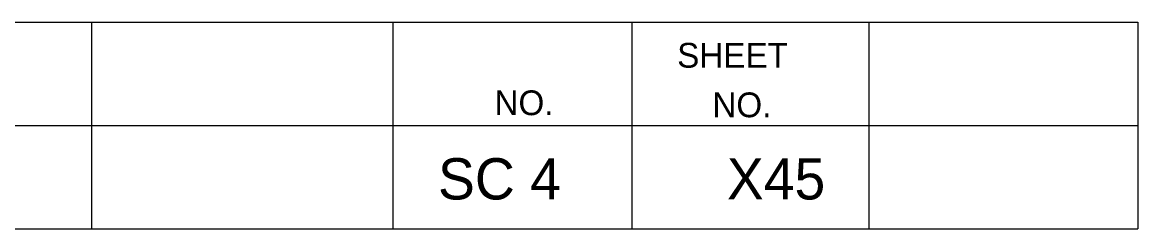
# Model space of a CAD drawing. Extents: x 1000 to 1162, y 999 to 8520.
# Drawn here: x 1148.08 to 1161.56, y 6160.05 to 6162.55 of the extents above; entities that cross this region are included whole.
import ezdxf

# ---------------------------------------------------------------- set-up
doc = ezdxf.new("R2010")
doc.units = 0
doc.layers.add('Level 20', color=7, linetype='Continuous')
doc.layers.add('Level 3', color=7, linetype='Continuous')

msp = doc.modelspace()

# ---------------------------------------------------------------- linework, layer by layer
at = {"layer": 'Level 3'}
for p, q in [((1133.055, 6162.546), (1161.555, 6162.546)), ((1133.055, 6162.546), (1161.555, 6162.546)), ((1133.055, 6162.546), (1161.555, 6162.546)), ((1133.055, 6162.546), (1161.555, 6162.546)), ((1133.055, 6162.546), (1161.555, 6162.546)), ((1133.055, 6162.546), (1161.555, 6162.546)), ((1133.055, 6162.546), (1161.555, 6162.546)), ((1133.055, 6162.546), (1161.555, 6162.546)), ((1133.055, 6162.546), (1161.555, 6162.546)), ((1133.055, 6162.546), (1161.555, 6162.546)), ((1133.055, 6162.546), (1161.555, 6162.546)), ((1133.055, 6162.546), (1161.555, 6162.546)), ((1133.055, 6162.546), (1161.555, 6162.546)), ((1133.055, 6162.546), (1161.555, 6162.546)), ((1133.055, 6162.546), (1161.555, 6162.546)), ((1133.055, 6162.546), (1161.555, 6162.546)), ((1133.055, 6162.546), (1161.555, 6162.546)), ((1133.055, 6162.546), (1161.555, 6162.546)), ((1133.055, 6162.546), (1161.555, 6162.546)), ((1133.055, 6162.546), (1161.555, 6162.546)), ((1133.055, 6162.546), (1161.555, 6162.546)), ((1133.055, 6162.546), (1161.555, 6162.546)), ((1133.055, 6162.546), (1161.555, 6162.546)), ((1133.055, 6162.546), (1161.555, 6162.546)), ((1133.055, 6162.546), (1161.555, 6162.546)), ((1133.055, 6162.546), (1161.555, 6162.546)), ((1133.055, 6162.546), (1161.555, 6162.546)), ((1133.055, 6162.546), (1161.555, 6162.546)), ((1133.055, 6162.546), (1161.555, 6162.546)), ((1133.055, 6162.546), (1161.555, 6162.546)), ((1133.055, 6162.546), (1161.555, 6162.546)), ((1133.055, 6162.546), (1161.555, 6162.546)), ((1133.055, 6162.546), (1161.555, 6162.546)), ((1133.055, 6162.546), (1161.555, 6162.546)), ((1133.055, 6162.546), (1161.555, 6162.546)), ((1133.055, 6162.546), (1161.555, 6162.546)), ((1133.055, 6162.546), (1161.555, 6162.546)), ((1133.055, 6162.546), (1161.555, 6162.546)), ((1133.055, 6162.546), (1161.555, 6162.546)), ((1133.055, 6162.546), (1161.555, 6162.546)), ((1133.055, 6162.546), (1161.555, 6162.546)), ((1133.055, 6162.546), (1161.555, 6162.546)), ((1133.055, 6162.546), (1161.555, 6162.546)), ((1148.913, 6162.546), (1148.913, 6160.046)), ((1148.913, 6162.546), (1148.913, 6160.046)), ((1148.913, 6162.546), (1148.913, 6160.046)), ((1148.913, 6162.546), (1148.913, 6160.046)), ((1148.913, 6162.546), (1148.913, 6160.046)), ((1148.913, 6162.546), (1148.913, 6160.046)), ((1148.913, 6162.546), (1148.913, 6160.046)), ((1148.913, 6162.546), (1148.913, 6160.046)), ((1148.913, 6162.546), (1148.913, 6160.046)), ((1148.913, 6162.546), (1148.913, 6160.046)), ((1148.913, 6162.546), (1148.913, 6160.046)), ((1148.913, 6162.546), (1148.913, 6160.046)), ((1148.913, 6162.546), (1148.913, 6160.046)), ((1148.913, 6162.546), (1148.913, 6160.046)), ((1148.913, 6162.546), (1148.913, 6160.046)), ((1148.913, 6162.546), (1148.913, 6160.046)), ((1148.913, 6162.546), (1148.913, 6160.046)), ((1148.913, 6162.546), (1148.913, 6160.046)), ((1148.913, 6162.546), (1148.913, 6160.046)), ((1148.913, 6162.546), (1148.913, 6160.046)), ((1148.913, 6162.546), (1148.913, 6160.046)), ((1148.913, 6162.546), (1148.913, 6160.046)), ((1148.913, 6162.546), (1148.913, 6160.046)), ((1148.913, 6162.546), (1148.913, 6160.046)), ((1148.913, 6162.546), (1148.913, 6160.046)), ((1148.913, 6162.546), (1148.913, 6160.046)), ((1148.913, 6162.546), (1148.913, 6160.046)), ((1148.913, 6162.546), (1148.913, 6160.046)), ((1148.913, 6162.546), (1148.913, 6160.046)), ((1148.913, 6162.546), (1148.913, 6160.046)), ((1148.913, 6162.546), (1148.913, 6160.046)), ((1148.913, 6162.546), (1148.913, 6160.046)), ((1148.913, 6162.546), (1148.913, 6160.046)), ((1148.913, 6162.546), (1148.913, 6160.046)), ((1148.913, 6162.546), (1148.913, 6160.046)), ((1148.913, 6162.546), (1148.913, 6160.046)), ((1148.913, 6162.546), (1148.913, 6160.046)), ((1148.913, 6162.546), (1148.913, 6160.046)), ((1148.913, 6162.546), (1148.913, 6160.046)), ((1148.913, 6162.546), (1148.913, 6160.046)), ((1148.913, 6162.546), (1148.913, 6160.046)), ((1148.913, 6162.546), (1148.913, 6160.046)), ((1148.913, 6162.546), (1148.913, 6160.046)), ((1152.554, 6162.546), (1152.554, 6160.046)), ((1152.554, 6162.546), (1152.554, 6160.046)), ((1152.554, 6162.546), (1152.554, 6160.046)), ((1152.554, 6162.546), (1152.554, 6160.046)), ((1152.554, 6162.546), (1152.554, 6160.046)), ((1152.554, 6162.546), (1152.554, 6160.046)), ((1152.554, 6162.546), (1152.554, 6160.046)), ((1152.554, 6162.546), (1152.554, 6160.046)), ((1152.554, 6162.546), (1152.554, 6160.046)), ((1152.554, 6162.546), (1152.554, 6160.046)), ((1152.554, 6162.546), (1152.554, 6160.046)), ((1152.554, 6162.546), (1152.554, 6160.046)), ((1152.554, 6162.546), (1152.554, 6160.046)), ((1152.554, 6162.546), (1152.554, 6160.046)), ((1152.554, 6162.546), (1152.554, 6160.046)), ((1152.554, 6162.546), (1152.554, 6160.046)), ((1152.554, 6162.546), (1152.554, 6160.046)), ((1152.554, 6162.546), (1152.554, 6160.046)), ((1152.554, 6162.546), (1152.554, 6160.046)), ((1152.554, 6162.546), (1152.554, 6160.046)), ((1152.554, 6162.546), (1152.554, 6160.046)), ((1152.554, 6162.546), (1152.554, 6160.046)), ((1152.554, 6162.546), (1152.554, 6160.046)), ((1152.554, 6162.546), (1152.554, 6160.046)), ((1152.554, 6162.546), (1152.554, 6160.046)), ((1152.554, 6162.546), (1152.554, 6160.046)), ((1152.554, 6162.546), (1152.554, 6160.046)), ((1152.554, 6162.546), (1152.554, 6160.046)), ((1152.554, 6162.546), (1152.554, 6160.046)), ((1152.554, 6162.546), (1152.554, 6160.046)), ((1152.554, 6162.546), (1152.554, 6160.046)), ((1152.554, 6162.546), (1152.554, 6160.046)), ((1152.554, 6162.546), (1152.554, 6160.046)), ((1152.554, 6162.546), (1152.554, 6160.046)), ((1152.554, 6162.546), (1152.554, 6160.046)), ((1152.554, 6162.546), (1152.554, 6160.046)), ((1152.554, 6162.546), (1152.554, 6160.046)), ((1152.554, 6162.546), (1152.554, 6160.046)), ((1152.554, 6162.546), (1152.554, 6160.046)), ((1152.554, 6162.546), (1152.554, 6160.046)), ((1152.554, 6162.546), (1152.554, 6160.046)), ((1152.554, 6162.546), (1152.554, 6160.046)), ((1152.554, 6162.546), (1152.554, 6160.046)), ((1155.44, 6162.546), (1155.44, 6160.046)), ((1155.44, 6162.546), (1155.44, 6160.046)), ((1155.44, 6162.546), (1155.44, 6160.046)), ((1155.44, 6162.546), (1155.44, 6160.046)), ((1155.44, 6162.546), (1155.44, 6160.046)), ((1155.44, 6162.546), (1155.44, 6160.046)), ((1155.44, 6162.546), (1155.44, 6160.046)), ((1155.44, 6162.546), (1155.44, 6160.046)), ((1155.44, 6162.546), (1155.44, 6160.046)), ((1155.44, 6162.546), (1155.44, 6160.046)), ((1155.44, 6162.546), (1155.44, 6160.046)), ((1155.44, 6162.546), (1155.44, 6160.046)), ((1155.44, 6162.546), (1155.44, 6160.046)), ((1155.44, 6162.546), (1155.44, 6160.046)), ((1155.44, 6162.546), (1155.44, 6160.046)), ((1155.44, 6162.546), (1155.44, 6160.046)), ((1155.44, 6162.546), (1155.44, 6160.046)), ((1155.44, 6162.546), (1155.44, 6160.046)), ((1155.44, 6162.546), (1155.44, 6160.046)), ((1155.44, 6162.546), (1155.44, 6160.046)), ((1155.44, 6162.546), (1155.44, 6160.046)), ((1155.44, 6162.546), (1155.44, 6160.046)), ((1155.44, 6162.546), (1155.44, 6160.046)), ((1155.44, 6162.546), (1155.44, 6160.046)), ((1155.44, 6162.546), (1155.44, 6160.046)), ((1155.44, 6162.546), (1155.44, 6160.046)), ((1155.44, 6162.546), (1155.44, 6160.046)), ((1155.44, 6162.546), (1155.44, 6160.046)), ((1155.44, 6162.546), (1155.44, 6160.046)), ((1155.44, 6162.546), (1155.44, 6160.046)), ((1155.44, 6162.546), (1155.44, 6160.046)), ((1155.44, 6162.546), (1155.44, 6160.046)), ((1155.44, 6162.546), (1155.44, 6160.046)), ((1155.44, 6162.546), (1155.44, 6160.046)), ((1155.44, 6162.546), (1155.44, 6160.046)), ((1155.44, 6162.546), (1155.44, 6160.046)), ((1155.44, 6162.546), (1155.44, 6160.046)), ((1155.44, 6162.546), (1155.44, 6160.046)), ((1155.44, 6162.546), (1155.44, 6160.046)), ((1155.44, 6162.546), (1155.44, 6160.046)), ((1155.44, 6162.546), (1155.44, 6160.046)), ((1155.44, 6162.546), (1155.44, 6160.046)), ((1155.44, 6162.546), (1155.44, 6160.046)), ((1158.305, 6162.546), (1158.305, 6160.046)), ((1158.305, 6162.546), (1158.305, 6160.046)), ((1158.305, 6162.546), (1158.305, 6160.046)), ((1158.305, 6162.546), (1158.305, 6160.046)), ((1158.305, 6162.546), (1158.305, 6160.046)), ((1158.305, 6162.546), (1158.305, 6160.046)), ((1158.305, 6162.546), (1158.305, 6160.046)), ((1158.305, 6162.546), (1158.305, 6160.046)), ((1158.305, 6162.546), (1158.305, 6160.046)), ((1158.305, 6162.546), (1158.305, 6160.046)), ((1158.305, 6162.546), (1158.305, 6160.046)), ((1158.305, 6162.546), (1158.305, 6160.046)), ((1158.305, 6162.546), (1158.305, 6160.046)), ((1158.305, 6162.546), (1158.305, 6160.046)), ((1158.305, 6162.546), (1158.305, 6160.046)), ((1158.305, 6162.546), (1158.305, 6160.046)), ((1158.305, 6162.546), (1158.305, 6160.046)), ((1158.305, 6162.546), (1158.305, 6160.046)), ((1158.305, 6162.546), (1158.305, 6160.046)), ((1158.305, 6162.546), (1158.305, 6160.046)), ((1158.305, 6162.546), (1158.305, 6160.046)), ((1158.305, 6162.546), (1158.305, 6160.046)), ((1158.305, 6162.546), (1158.305, 6160.046)), ((1158.305, 6162.546), (1158.305, 6160.046)), ((1158.305, 6162.546), (1158.305, 6160.046)), ((1158.305, 6162.546), (1158.305, 6160.046)), ((1158.305, 6162.546), (1158.305, 6160.046)), ((1158.305, 6162.546), (1158.305, 6160.046)), ((1158.305, 6162.546), (1158.305, 6160.046)), ((1158.305, 6162.546), (1158.305, 6160.046)), ((1158.305, 6162.546), (1158.305, 6160.046)), ((1158.305, 6162.546), (1158.305, 6160.046)), ((1158.305, 6162.546), (1158.305, 6160.046)), ((1158.305, 6162.546), (1158.305, 6160.046)), ((1158.305, 6162.546), (1158.305, 6160.046)), ((1158.305, 6162.546), (1158.305, 6160.046)), ((1158.305, 6162.546), (1158.305, 6160.046)), ((1158.305, 6162.546), (1158.305, 6160.046)), ((1158.305, 6162.546), (1158.305, 6160.046)), ((1158.305, 6162.546), (1158.305, 6160.046)), ((1158.305, 6162.546), (1158.305, 6160.046)), ((1158.305, 6162.546), (1158.305, 6160.046)), ((1158.305, 6162.546), (1158.305, 6160.046)), ((1161.555, 6162.546), (1161.555, 6160.046)), ((1161.555, 6162.546), (1161.555, 6160.046)), ((1161.555, 6162.546), (1161.555, 6160.046)), ((1161.555, 6162.546), (1161.555, 6160.046)), ((1161.555, 6162.546), (1161.555, 6160.046)), ((1161.555, 6162.546), (1161.555, 6160.046)), ((1161.555, 6162.546), (1161.555, 6160.046)), ((1161.555, 6162.546), (1161.555, 6160.046)), ((1161.555, 6162.546), (1161.555, 6160.046)), ((1161.555, 6162.546), (1161.555, 6160.046)), ((1161.555, 6162.546), (1161.555, 6160.046)), ((1161.555, 6162.546), (1161.555, 6160.046)), ((1161.555, 6162.546), (1161.555, 6160.046)), ((1161.555, 6162.546), (1161.555, 6160.046)), ((1161.555, 6162.546), (1161.555, 6160.046)), ((1161.555, 6162.546), (1161.555, 6160.046)), ((1161.555, 6162.546), (1161.555, 6160.046)), ((1161.555, 6162.546), (1161.555, 6160.046)), ((1161.555, 6162.546), (1161.555, 6160.046)), ((1161.555, 6162.546), (1161.555, 6160.046)), ((1161.555, 6162.546), (1161.555, 6160.046)), ((1161.555, 6162.546), (1161.555, 6160.046)), ((1161.555, 6162.546), (1161.555, 6160.046)), ((1161.555, 6162.546), (1161.555, 6160.046)), ((1161.555, 6162.546), (1161.555, 6160.046)), ((1161.555, 6162.546), (1161.555, 6160.046)), ((1161.555, 6162.546), (1161.555, 6160.046)), ((1161.555, 6162.546), (1161.555, 6160.046)), ((1161.555, 6162.546), (1161.555, 6160.046)), ((1161.555, 6162.546), (1161.555, 6160.046)), ((1161.555, 6162.546), (1161.555, 6160.046)), ((1161.555, 6162.546), (1161.555, 6160.046)), ((1161.555, 6162.546), (1161.555, 6160.046)), ((1161.555, 6162.546), (1161.555, 6160.046)), ((1161.555, 6162.546), (1161.555, 6160.046)), ((1161.555, 6162.546), (1161.555, 6160.046)), ((1161.555, 6162.546), (1161.555, 6160.046)), ((1161.555, 6162.546), (1161.555, 6160.046)), ((1161.555, 6162.546), (1161.555, 6160.046)), ((1161.555, 6162.546), (1161.555, 6160.046)), ((1161.555, 6162.546), (1161.555, 6160.046)), ((1161.555, 6162.546), (1161.555, 6160.046)), ((1161.555, 6162.546), (1161.555, 6160.046)), ((1133.055, 6161.296), (1161.555, 6161.296)), ((1133.055, 6161.296), (1161.555, 6161.296)), ((1133.055, 6161.296), (1161.555, 6161.296)), ((1133.055, 6161.296), (1161.555, 6161.296)), ((1133.055, 6161.296), (1161.555, 6161.296)), ((1133.055, 6161.296), (1161.555, 6161.296)), ((1133.055, 6161.296), (1161.555, 6161.296)), ((1133.055, 6161.296), (1161.555, 6161.296)), ((1133.055, 6161.296), (1161.555, 6161.296)), ((1133.055, 6161.296), (1161.555, 6161.296)), ((1133.055, 6161.296), (1161.555, 6161.296)), ((1133.055, 6161.296), (1161.555, 6161.296)), ((1133.055, 6161.296), (1161.555, 6161.296)), ((1133.055, 6161.296), (1161.555, 6161.296)), ((1133.055, 6161.296), (1161.555, 6161.296)), ((1133.055, 6161.296), (1161.555, 6161.296)), ((1133.055, 6161.296), (1161.555, 6161.296)), ((1133.055, 6161.296), (1161.555, 6161.296)), ((1133.055, 6161.296), (1161.555, 6161.296)), ((1133.055, 6161.296), (1161.555, 6161.296)), ((1133.055, 6161.296), (1161.555, 6161.296)), ((1133.055, 6161.296), (1161.555, 6161.296)), ((1133.055, 6161.296), (1161.555, 6161.296)), ((1133.055, 6161.296), (1161.555, 6161.296)), ((1133.055, 6161.296), (1161.555, 6161.296)), ((1133.055, 6161.296), (1161.555, 6161.296)), ((1133.055, 6161.296), (1161.555, 6161.296)), ((1133.055, 6161.296), (1161.555, 6161.296)), ((1133.055, 6161.296), (1161.555, 6161.296)), ((1133.055, 6161.296), (1161.555, 6161.296)), ((1133.055, 6161.296), (1161.555, 6161.296)), ((1133.055, 6161.296), (1161.555, 6161.296)), ((1133.055, 6161.296), (1161.555, 6161.296)), ((1133.055, 6161.296), (1161.555, 6161.296)), ((1133.055, 6161.296), (1161.555, 6161.296)), ((1133.055, 6161.296), (1161.555, 6161.296)), ((1133.055, 6161.296), (1161.555, 6161.296)), ((1133.055, 6161.296), (1161.555, 6161.296)), ((1133.055, 6161.296), (1161.555, 6161.296)), ((1133.055, 6161.296), (1161.555, 6161.296)), ((1133.055, 6161.296), (1161.555, 6161.296)), ((1133.055, 6161.296), (1161.555, 6161.296)), ((1133.055, 6161.296), (1161.555, 6161.296)), ((1133.055, 6160.046), (1161.555, 6160.046)), ((1133.055, 6160.046), (1161.555, 6160.046)), ((1133.055, 6160.046), (1161.555, 6160.046)), ((1133.055, 6160.046), (1161.555, 6160.046)), ((1133.055, 6160.046), (1161.555, 6160.046)), ((1133.055, 6160.046), (1161.555, 6160.046)), ((1133.055, 6160.046), (1161.555, 6160.046)), ((1133.055, 6160.046), (1161.555, 6160.046)), ((1133.055, 6160.046), (1161.555, 6160.046)), ((1133.055, 6160.046), (1161.555, 6160.046)), ((1133.055, 6160.046), (1161.555, 6160.046)), ((1133.055, 6160.046), (1161.555, 6160.046)), ((1133.055, 6160.046), (1161.555, 6160.046)), ((1133.055, 6160.046), (1161.555, 6160.046)), ((1133.055, 6160.046), (1161.555, 6160.046)), ((1133.055, 6160.046), (1161.555, 6160.046)), ((1133.055, 6160.046), (1161.555, 6160.046)), ((1133.055, 6160.046), (1161.555, 6160.046)), ((1133.055, 6160.046), (1161.555, 6160.046)), ((1133.055, 6160.046), (1161.555, 6160.046)), ((1133.055, 6160.046), (1161.555, 6160.046)), ((1133.055, 6160.046), (1161.555, 6160.046)), ((1133.055, 6160.046), (1161.555, 6160.046)), ((1133.055, 6160.046), (1161.555, 6160.046)), ((1133.055, 6160.046), (1161.555, 6160.046)), ((1133.055, 6160.046), (1161.555, 6160.046)), ((1133.055, 6160.046), (1161.555, 6160.046)), ((1133.055, 6160.046), (1161.555, 6160.046)), ((1133.055, 6160.046), (1161.555, 6160.046)), ((1133.055, 6160.046), (1161.555, 6160.046)), ((1133.055, 6160.046), (1161.555, 6160.046)), ((1133.055, 6160.046), (1161.555, 6160.046)), ((1133.055, 6160.046), (1161.555, 6160.046)), ((1133.055, 6160.046), (1161.555, 6160.046)), ((1133.055, 6160.046), (1161.555, 6160.046)), ((1133.055, 6160.046), (1161.555, 6160.046)), ((1133.055, 6160.046), (1161.555, 6160.046)), ((1133.055, 6160.046), (1161.555, 6160.046)), ((1133.055, 6160.046), (1161.555, 6160.046)), ((1133.055, 6160.046), (1161.555, 6160.046)), ((1133.055, 6160.046), (1161.555, 6160.046)), ((1133.055, 6160.046), (1161.555, 6160.046)), ((1133.055, 6160.046), (1161.555, 6160.046))]:
    msp.add_line(p, q, dxfattribs=at)

# ---------------------------------------------------------------- texts
at = {"layer": 'Level 20'}
for s, p in [('SC 4', (1153.099, 6160.4)), ('X45', (1156.59, 6160.4))]:
    msp.add_text(s, height=0.5, dxfattribs=at).set_placement(p)
at = {"layer": 'Level 3'}
for s, p in [('SHEET', (1155.99, 6161.996)), ('SHEET', (1155.99, 6161.996)), ('SHEET', (1155.99, 6161.996)), ('SHEET', (1155.99, 6161.996)), ('SHEET', (1155.99, 6161.996)), ('SHEET', (1155.99, 6161.996)), ('SHEET', (1155.99, 6161.996)), ('SHEET', (1155.99, 6161.996)), ('SHEET', (1155.99, 6161.996)), ('SHEET', (1155.99, 6161.996)), ('SHEET', (1155.99, 6161.996)), ('SHEET', (1155.99, 6161.996)), ('SHEET', (1155.99, 6161.996)), ('SHEET', (1155.99, 6161.996)), ('SHEET', (1155.99, 6161.996)), ('SHEET', (1155.99, 6161.996)), ('SHEET', (1155.99, 6161.996)), ('SHEET', (1155.99, 6161.996)), ('SHEET', (1155.99, 6161.996)), ('SHEET', (1155.99, 6161.996)), ('SHEET', (1155.99, 6161.996)), ('SHEET', (1155.99, 6161.996)), ('SHEET', (1155.99, 6161.996)), ('SHEET', (1155.99, 6161.996)), ('SHEET', (1155.99, 6161.996)), ('SHEET', (1155.99, 6161.996)), ('SHEET', (1155.99, 6161.996)), ('SHEET', (1155.99, 6161.996)), ('SHEET', (1155.99, 6161.996)), ('SHEET', (1155.99, 6161.996)), ('SHEET', (1155.99, 6161.996)), ('SHEET', (1155.99, 6161.996)), ('SHEET', (1155.99, 6161.996)), ('SHEET', (1155.99, 6161.996)), ('SHEET', (1155.99, 6161.996)), ('SHEET', (1155.99, 6161.996)), ('SHEET', (1155.99, 6161.996)), ('SHEET', (1155.99, 6161.996)), ('SHEET', (1155.99, 6161.996)), ('SHEET', (1155.99, 6161.996)), ('SHEET', (1155.99, 6161.996)), ('SHEET', (1155.99, 6161.996)), ('SHEET', (1155.99, 6161.996)), ('NO.', (1153.782, 6161.421)), ('NO.', (1153.782, 6161.421)), ('NO.', (1153.782, 6161.421)), ('NO.', (1153.782, 6161.421)), ('NO.', (1153.782, 6161.421)), ('NO.', (1153.782, 6161.421)), ('NO.', (1153.782, 6161.421)), ('NO.', (1153.782, 6161.421)), ('NO.', (1153.782, 6161.421)), ('NO.', (1153.782, 6161.421)), ('NO.', (1153.782, 6161.421)), ('NO.', (1153.782, 6161.421)), ('NO.', (1153.782, 6161.421)), ('NO.', (1153.782, 6161.421)), ('NO.', (1153.782, 6161.421)), ('NO.', (1153.782, 6161.421)), ('NO.', (1153.782, 6161.421)), ('NO.', (1153.782, 6161.421)), ('NO.', (1153.782, 6161.421)), ('NO.', (1153.782, 6161.421)), ('NO.', (1153.782, 6161.421)), ('NO.', (1153.782, 6161.421)), ('NO.', (1153.782, 6161.421)), ('NO.', (1153.782, 6161.421)), ('NO.', (1153.782, 6161.421)), ('NO.', (1153.782, 6161.421)), ('NO.', (1153.782, 6161.421)), ('NO.', (1153.782, 6161.421)), ('NO.', (1153.782, 6161.421)), ('NO.', (1153.782, 6161.421)), ('NO.', (1153.782, 6161.421)), ('NO.', (1153.782, 6161.421)), ('NO.', (1153.782, 6161.421)), ('NO.', (1153.782, 6161.421)), ('NO.', (1153.782, 6161.421)), ('NO.', (1153.782, 6161.421)), ('NO.', (1153.782, 6161.421)), ('NO.', (1153.782, 6161.421)), ('NO.', (1153.782, 6161.421)), ('NO.', (1153.782, 6161.421)), ('NO.', (1153.782, 6161.421)), ('NO.', (1153.782, 6161.421)), ('NO.', (1153.782, 6161.421)), ('NO.', (1156.415, 6161.396)), ('NO.', (1156.415, 6161.396)), ('NO.', (1156.415, 6161.396)), ('NO.', (1156.415, 6161.396)), ('NO.', (1156.415, 6161.396)), ('NO.', (1156.415, 6161.396)), ('NO.', (1156.415, 6161.396)), ('NO.', (1156.415, 6161.396)), ('NO.', (1156.415, 6161.396)), ('NO.', (1156.415, 6161.396)), ('NO.', (1156.415, 6161.396)), ('NO.', (1156.415, 6161.396)), ('NO.', (1156.415, 6161.396)), ('NO.', (1156.415, 6161.396)), ('NO.', (1156.415, 6161.396)), ('NO.', (1156.415, 6161.396)), ('NO.', (1156.415, 6161.396)), ('NO.', (1156.415, 6161.396)), ('NO.', (1156.415, 6161.396)), ('NO.', (1156.415, 6161.396)), ('NO.', (1156.415, 6161.396)), ('NO.', (1156.415, 6161.396)), ('NO.', (1156.415, 6161.396)), ('NO.', (1156.415, 6161.396)), ('NO.', (1156.415, 6161.396)), ('NO.', (1156.415, 6161.396)), ('NO.', (1156.415, 6161.396)), ('NO.', (1156.415, 6161.396)), ('NO.', (1156.415, 6161.396)), ('NO.', (1156.415, 6161.396)), ('NO.', (1156.415, 6161.396)), ('NO.', (1156.415, 6161.396)), ('NO.', (1156.415, 6161.396)), ('NO.', (1156.415, 6161.396)), ('NO.', (1156.415, 6161.396)), ('NO.', (1156.415, 6161.396)), ('NO.', (1156.415, 6161.396)), ('NO.', (1156.415, 6161.396)), ('NO.', (1156.415, 6161.396)), ('NO.', (1156.415, 6161.396)), ('NO.', (1156.415, 6161.396)), ('NO.', (1156.415, 6161.396)), ('NO.', (1156.415, 6161.396))]:
    msp.add_text(s, height=0.3, dxfattribs=at).set_placement(p)

doc.saveas('drawing.dxf')
